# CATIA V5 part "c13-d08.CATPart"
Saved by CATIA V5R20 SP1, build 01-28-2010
Part number: Part1
Material "Alpine Fir": density 500 kg/m3, Young's modulus 1.7e+10 Pa, Poisson ratio 0.45, thermal expansion 3.75e-06 1/K
Bounding box of the stored display mesh (mm): x -163 to 95, y -77.362 to 77.362, z -85 to 85
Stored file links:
  D:\v5_r20\psrt_files_downloaded\c13-catia-v5r20-prt\c13-catia-v5r20-figr-13-29 & 30\c13-d08.CATPart
  C:\Program Files (x86)\Dassault Systemes\B20\intel_a\startup\materials\Catalog.CATMaterial
  C:\Program Files (x86)\Dassault Systemes\B20\intel_a\startup\materials\alpin_fir.jpg
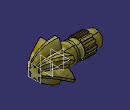
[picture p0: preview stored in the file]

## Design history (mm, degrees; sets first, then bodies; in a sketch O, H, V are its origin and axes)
Set1
  Plane1: type Offset, RefPlane face of Shaft1, Offset 45, reversed
  Plane2: type Offset, RefPlane Plane1, Offset 50, reversed
Body1 (main body), material "Alpine Fir"
  Sketch1 on zx-plane, origin (0, 0, 0), H (-1, 0, 0), V (0, 0, 1)
    axis line L1 (0, 0) -> (170, 0)
    line L2 (0, 0) -> (0, -45)
    point P2 (0, -45)
    line L3 (0, -45) -> (5, -45)
    point P3 (5, -45)
    line L4 (5, -45) -> (5, -39)
    line L5 (5, -39) -> (51, -39)
    line L6 (51, -39) -> (51, -38)
    point P6 (51, -38)
    line L7 (51, -38) -> (61, -38)
    point P7 (61, -38)
    line L8 (61, -38) -> (61, -36)
    point P8 (61, -36)
    arc A1 centre (72, -36) radius 11 from (61, -36) to (83, -36) cw
    point P10 (83, -36)
    line L9 (83, -36) -> (131, -36)
    line L10 (131, -36) -> (131, -32.5)
    line L11 (131, -32.5) -> (163, -32.5)
    line L12 (163, -32.5) -> (163, 0)
    point P14 (163, 0)
    line L13 (163, 0) -> (0, 0)
    "Radius" L11 L1 = 32.5
    "Radius" L9 L1 = 36
    "Radius" P7 L1 = 38
    "Radius" L5 L1 = 39
    "Radius" P3 L1 = 45
    length L11 = 32
    length L9 = 48
    distance P10 P8 = 22
    distance P7 P6 = 10
    length L5 = 46
    distance P3 P2 = 5
    horizontal: L1 H, L3 H, L5 H, L7 H, L9 H, L11 H, L13 H
    vertical: L2 V, L4 V, L6 V, L8 V, L12 V, L10 V
    tangency: A1 L8
    coincidence: P14 L1
  Shaft1: profile Sketch1, axis Sketch1.L1, angle 360
  Sketch2 on face of Shaft1, origin (-131, 0, 0), H (0, -1, 0), V (0, 0, 1)
    projected circle E1 centre (0, 0) radius 36 from edge [face of Shaft1 | face of Shaft1]
    projected arc E2 centre (0, 0) radius 36 from (5, 35.6511) to (-5, 35.6511) ccw from edge [face of Shaft1 | face of Shaft1]
    axis line L1 (0, 0) -> (0, 17.1744)
    point P2 (-5, 35.6511)
    line L2 (-5, 35.6511) -> (-5, 40.6511)
    point P3 (-5, 40.6511)
    line L3 (-5, 40.6511) -> (0, 40.6511)
    point P4 (0, 40.6511)
    point P5 (0, 40.6511)
    point P6 (5, 40.6511)
    line L4 (5, 40.6511) -> (0, 40.6511)
    point P7 (5, 35.6511)
    line L5 (5, 35.6511) -> (5, 40.6511)
    length L5 = 5
    distance L5 L2 = 10
    vertical: L1 V, L2 V
    coincidence: P2 E1, P4 L1, P4 P5
    horizontal: L3 H
    symmetry: P4 P5 L1, P3 P6 L1, L3 L4 L1, P2 P7 L1, L2 L5 L1
  Pad1: profile Sketch2, direction (1, 0, 0), length 48
  CircPattern1: of Pad1, instances 13, angular step 27.6923 {= 360.0*1 deg/CircPattern1.AngularNumber}, axis from face of Shaft1
  Loft1: solid, Sections (Sketch5; Sketch4; Sketch3)
  Sketch3 on Plane2, origin (95, 0, 0), H (0, -1, 0), V (0, 0, 1)
    construction line L1 through (0, 0) direction (1, 0)
    construction line L2 through (0, 0) direction (0, 1)
    arc A1 centre (23.3627, 6.7195) radius 24.375 from (13.5018, 29.0108) to (2.0971, 18.6324) ccw
    line L3 (18.3732, 26.1983) -> (13.5018, 29.0108)
    arc A2 centre (-5.8621, 23.5924) radius 24.375 from (15.0875, 11.1324) to (18.3732, 26.1983) ccw
    arc A3 centre (0, 0) radius 18.75 from (17.1847, 7.5) to (15.0875, 11.1324) ccw
    arc A4 centre (17.5006, -16.873) radius 24.375 from (31.875, 2.8125) to (17.1847, 7.5) ccw
    line L4 (31.875, -2.8125) -> (31.875, 2.8125)
    arc A5 centre (17.5006, 16.873) radius 24.375 from (17.1847, -7.5) to (31.875, -2.8125) ccw
    arc A6 centre (0, 0) radius 18.75 from (15.0875, -11.1324) to (17.1847, -7.5) ccw
    arc A7 centre (-5.8621, -23.5924) radius 24.375 from (18.3732, -26.1983) to (15.0875, -11.1324) ccw
    line L5 (13.5018, -29.0108) -> (18.3732, -26.1983)
    arc A8 centre (23.3627, -6.7195) radius 24.375 from (2.0971, -18.6324) to (13.5018, -29.0108) ccw
    arc A9 centre (0, 0) radius 18.75 from (-2.0971, -18.6324) to (2.0971, -18.6324) ccw
    arc A10 centre (-23.3627, -6.7195) radius 24.375 from (-13.5018, -29.0108) to (-2.0971, -18.6324) ccw
    line L6 (-18.3732, -26.1983) -> (-13.5018, -29.0108)
    arc A11 centre (5.8621, -23.5924) radius 24.375 from (-15.0875, -11.1324) to (-18.3732, -26.1983) ccw
    arc A12 centre (0, 0) radius 18.75 from (-17.1847, -7.5) to (-15.0875, -11.1324) ccw
    arc A13 centre (-17.5006, 16.873) radius 24.375 from (-31.875, -2.8125) to (-17.1847, -7.5) ccw
    line L7 (-31.875, 2.8125) -> (-31.875, -2.8125)
    arc A14 centre (-17.5006, -16.873) radius 24.375 from (-17.1847, 7.5) to (-31.875, 2.8125) ccw
    arc A15 centre (0, 0) radius 18.75 from (-15.0875, 11.1324) to (-17.1847, 7.5) ccw
    arc A16 centre (5.8621, 23.5924) radius 24.375 from (-18.3732, 26.1983) to (-15.0875, 11.1324) ccw
    line L8 (-13.5018, 29.0108) -> (-18.3732, 26.1983)
    arc A17 centre (-23.3627, 6.7195) radius 24.375 from (-2.0971, 18.6324) to (-13.5018, 29.0108) ccw
    arc A18 centre (0, 0) radius 18.75 from (2.0971, 18.6324) to (-2.0971, 18.6324) ccw
  Sketch4 on Plane1, origin (45, 0, 0), H (0, -1, 0), V (0, 0, 1)
    construction line L1 through (0, 0) direction (0.9659, -0.2588)
    construction line L2 through (0, 0) direction (0.2588, 0.9659)
    arc A1 centre (0, 0) radius 37.5 from (5.5935, -37.0805) to (13.6962, -34.9094) ccw
    arc A2 centre (-41.655, -25.0745) radius 48.75 from (-11.0664, -63.0336) to (5.5935, -37.0805) ccw
    arc A3 centre (48.6115, -0.8876) radius 48.75 from (13.6962, -34.9094) to (41.1006, -49.0555) ccw
    line L3 (49.0555, -41.1006) -> (41.1006, -49.0555)
    arc A4 centre (0.8876, -48.6115) radius 48.75 from (49.0555, -41.1006) to (34.9094, -13.6962) ccw
    arc A5 centre (0, 0) radius 37.5 from (34.9094, -13.6962) to (37.0805, -5.5935) ccw
    arc A6 centre (25.0745, 41.655) radius 48.75 from (37.0805, -5.5935) to (63.0336, 11.0664) ccw
    line L4 (60.1219, 21.933) -> (63.0336, 11.0664)
    arc A7 centre (42.5426, -23.5371) radius 48.75 from (60.1219, 21.933) to (29.3159, 23.3843) ccw
    arc A8 centre (0, 0) radius 37.5 from (29.3159, 23.3843) to (23.3843, 29.3159) ccw
    arc A9 centre (-23.5371, 42.5426) radius 48.75 from (23.3843, 29.3159) to (21.933, 60.1219) ccw
    line L5 (11.0664, 63.0336) -> (21.933, 60.1219)
    arc A10 centre (41.655, 25.0745) radius 48.75 from (11.0664, 63.0336) to (-5.5935, 37.0805) ccw
    arc A11 centre (0, 0) radius 37.5 from (-5.5935, 37.0805) to (-13.6962, 34.9094) ccw
    arc A12 centre (-48.6115, 0.8876) radius 48.75 from (-13.6962, 34.9094) to (-41.1006, 49.0555) ccw
    line L6 (-49.0555, 41.1006) -> (-41.1006, 49.0555)
    arc A13 centre (-0.8876, 48.6115) radius 48.75 from (-49.0555, 41.1006) to (-34.9094, 13.6962) ccw
    arc A14 centre (0, 0) radius 37.5 from (-34.9094, 13.6962) to (-37.0805, 5.5935) ccw
    arc A15 centre (-25.0745, -41.655) radius 48.75 from (-37.0805, 5.5935) to (-63.0336, -11.0664) ccw
    line L7 (-60.1219, -21.933) -> (-63.0336, -11.0664)
    arc A16 centre (-42.5426, 23.5371) radius 48.75 from (-60.1219, -21.933) to (-29.3159, -23.3843) ccw
    arc A17 centre (0, 0) radius 37.5 from (-29.3159, -23.3843) to (-23.3843, -29.3159) ccw
    arc A18 centre (23.5371, -42.5426) radius 48.75 from (-23.3843, -29.3159) to (-21.933, -60.1219) ccw
    line L8 (-11.0664, -63.0336) -> (-21.933, -60.1219)
  Sketch5 on face of Shaft1, origin (0, 0, 0), H (0, 1, 0), V (0, 0, 1)
    arc A1 centre (44.9945, 46.6682) radius 65 from (-20, 45.8258) to (-7.5, 85) cw
    point P1 (-7.5, 85)
    point P2 (7.5, 85)
    arc A2 centre (-44.9945, 46.6682) radius 65 from (20, 45.8258) to (7.5, 85) ccw
    line L1 (-7.5, 85) -> (7.5, 85)
    point P3 (7.5, 85)
    point P4 (20, 45.8258)
    point P5 (-20, 45.8258)
    point P6 (0, 0)
    arc A3 centre (0, 0) radius 50 from (29.6863, 40.2334) to (20, 45.8258) ccw
    arc A4 centre (-17.9186, 62.3005) radius 65 from (-49.6863, 5.5924) to (-77.3622, 36.0048) cw
    arc A5 centre (-62.9132, -15.6323) radius 65 from (-29.6863, 40.2334) to (-69.8622, 48.9952) ccw
    line L2 (-77.3622, 36.0048) -> (-69.8622, 48.9952)
    arc A6 centre (-62.9132, 15.6323) radius 65 from (-29.6863, -40.2334) to (-69.8622, -48.9952) cw
    arc A7 centre (-17.9186, -62.3005) radius 65 from (-49.6863, -5.5924) to (-77.3622, -36.0048) ccw
    line L3 (-69.8622, -48.9952) -> (-77.3622, -36.0048)
    arc A8 centre (-44.9945, -46.6682) radius 65 from (20, -45.8258) to (7.5, -85) cw
    arc A9 centre (44.9945, -46.6682) radius 65 from (-20, -45.8258) to (-7.5, -85) ccw
    line L4 (7.5, -85) -> (-7.5, -85)
    arc A10 centre (17.9186, -62.3005) radius 65 from (49.6863, -5.5924) to (77.3622, -36.0048) cw
    arc A11 centre (62.9132, 15.6323) radius 65 from (29.6863, -40.2334) to (69.8622, -48.9952) ccw
    line L5 (77.3622, -36.0048) -> (69.8622, -48.9952)
    arc A12 centre (62.9132, -15.6323) radius 65 from (29.6863, 40.2334) to (69.8622, 48.9952) cw
    arc A13 centre (17.9186, 62.3005) radius 65 from (49.6863, 5.5924) to (77.3622, 36.0048) ccw
    line L6 (69.8622, 48.9952) -> (77.3622, 36.0048)
    arc A14 centre (0, 0) radius 50 from (-49.6863, 5.5924) to (-49.6863, -5.5924) ccw
    arc A15 centre (0, 0) radius 50 from (-29.6863, -40.2334) to (-20, -45.8258) ccw
    arc A16 centre (0, 0) radius 50 from (20, -45.8258) to (29.6863, -40.2334) ccw
    arc A17 centre (0, 0) radius 50 from (49.6863, -5.5924) to (49.6863, 5.5924) ccw
    arc A18 centre (0, 0) radius 50 from (-20, 45.8258) to (-29.6863, 40.2334) ccw
    distance P4 P5 = 40
    radius A2 = 65
    length L1 = 15
    distance P6 L1 = 85
    radius A3 = 50
    symmetry: P1 P2 V, A1 A2 V, P4 P5 V
    coincidence: P3 A2, P6 O, P5 A3, A3 A14, A14 A15, A15 A16, A16 A17, A3 A18
    horizontal: L1 H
